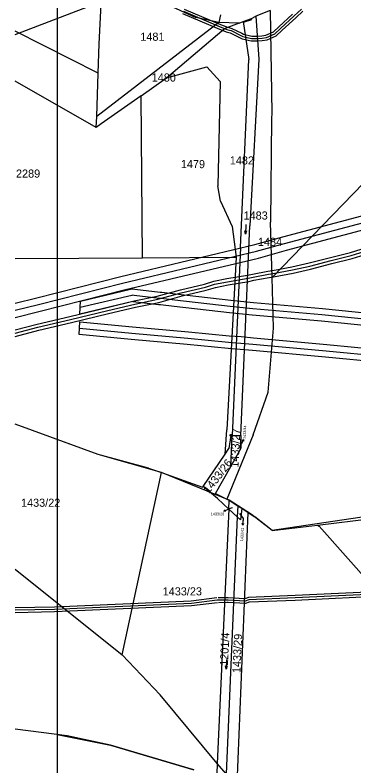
# Model space of a CAD drawing. Extents: x -510185 to -506993, y -1126306 to -1123642.
# Drawn here: x -510185 to -509972.3, y -1125827.4 to -1125355.5 of the extents above; entities that cross this region are included whole.
import ezdxf

# ---------------------------------------------------------------- set-up
doc = ezdxf.new("R2010")
doc.units = 0
for name, color, linetype in [('Net4gas', 7, 'Continuous'), ('parcelni hranice', 7, 'Continuous'), ('telefonica', 7, 'Continuous'), ('u_dalnice', 7, 'Continuous'), ('u_kabely', 7, 'Continuous'), ('u_net4gas', 7, 'Continuous'), ('u_plyn ochranné pásmo', 7, 'Continuous'), ('u_plyn VTL', 7, 'Continuous'), ('u_sitel_self_net4', 7, 'Continuous'), ('u_Telefonica', 7, 'Continuous'), ('x_formát_rám', 7, 'Continuous'), ('ČEPS', 7, 'Continuous'), ('ˇ2', 7, 'Continuous'), ('ˇ3', 7, 'Continuous'), ('ˇ4', 7, 'Continuous'), ('ˇ7', 7, 'Continuous'), ('ˇ8', 7, 'Continuous')]:
    doc.layers.add(name, color=color, linetype=linetype)

msp = doc.modelspace()

# ---------------------------------------------------------------- linework, layer by layer
at = {"layer": 'Net4gas'}
for points in [[(-510185.05, -1125536.53), (-510171.45, -1125533.15), (-510118.64, -1125519.73), (-510034.51, -1125499.78), (-510017.05, -1125494.96), (-509964.2, -1125480.91), (-509918.3, -1125468.33), (-509886.05, -1125459.17), (-509862.65, -1125451.75), (-509848.66, -1125447.37)], [(-510185.05, -1125545.5), (-510169.33, -1125541.59), (-510116.57, -1125528.18), (-510032.35, -1125508.21), (-510014.78, -1125503.35), (-509961.93, -1125489.31), (-509915.96, -1125476.71), (-509883.55, -1125467.5), (-509860.03, -1125460.04), (-509848.72, -1125456.5), (-509843.6, -1125454.45), (-509839.38, -1125452.47), (-509835.66, -1125450.19)]]:
    msp.add_lwpolyline(points, dxfattribs=at)
at = {"layer": 'parcelni hranice'}
for p, q in [((-510132.16, -1125373.62), (-510129.92, -1125327.14)), ((-510096.36, -1125345.63), (-510071.49, -1125357.11)), ((-510025, -1125352.59), (-510033.87, -1125356.33)), ((-510025, -1125352.59), (-510023.92, -1125417.04)), ((-510057.09, -1125360.29), (-510071.49, -1125357.11)), ((-510056.1, -1125355.49), (-510057.09, -1125360.29)), ((-510041.95, -1125359.51), (-510036.6, -1125357.7)), ((-510036.6, -1125357.7), (-510033.87, -1125356.33)), ((-510033.87, -1125356.33), (-510032.03, -1125383.35)), ((-510057.09, -1125360.29), (-510133.77, -1125419.38)), ((-510044.29, -1125360.72), (-510057.09, -1125360.29)), ((-510044.29, -1125360.72), (-510053.82, -1125364.11)), ((-510044.29, -1125360.72), (-510041.95, -1125359.51)), ((-510041.95, -1125359.51), (-510038.29, -1125383.47)), ((-510132.81, -1125392.03), (-510185.05, -1125365.7)), ((-510090, -1125395), (-510053.82, -1125364.11)), ((-510132.81, -1125392.03), (-510132.16, -1125373.62)), ((-510043.54, -1125501.56), (-510038.29, -1125383.47)), ((-510032.03, -1125383.35), (-510037.65, -1125487.99)), ((-510133.77, -1125419.38), (-510132.81, -1125392.03)), ((-510090, -1125395), (-510064.59, -1125388.14)), ((-510064.59, -1125388.14), (-510056.37, -1125397.34)), ((-510105.97, -1125406.29), (-510090, -1125395)), ((-510134.23, -1125426.27), (-510185.05, -1125397.03)), ((-510056.37, -1125397.34), (-510057.72, -1125462.78)), ((-510105.97, -1125406.29), (-510130.91, -1125423.92)), ((-510105.03, -1125508.07), (-510105.97, -1125406.29)), ((-510134.23, -1125426.27), (-510133.77, -1125419.38)), ((-510023.92, -1125417.04), (-510024.09, -1125420.78)), ((-510130.91, -1125423.92), (-510134.23, -1125426.27)), ((-510024.09, -1125420.78), (-510024.78, -1125485.7)), ((-510056.06, -1125472.49), (-510057.72, -1125462.78)), ((-510023.75, -1125520.46), (-509966.3, -1125461.11)), ((-510056.06, -1125472.49), (-510048.68, -1125488.4)), ((-510023.75, -1125520.46), (-510024.78, -1125485.7)), ((-510048.68, -1125488.4), (-510046.34, -1125507.71)), ((-510043.38, -1125619.76), (-510037.65, -1125487.99)), ((-510043.54, -1125501.56), (-510048.8, -1125619.64)), ((-510185.05, -1125508.57), (-510105.03, -1125508.07)), ((-510105.03, -1125508.07), (-510046.34, -1125507.71)), ((-510046.34, -1125507.71), (-510052.18, -1125616.15)), ((-510022.8, -1125552.26), (-510023.75, -1125520.46)), ((-510026.11, -1125592.58), (-510022.8, -1125552.26)), ((-510035.59, -1125619.37), (-510026.11, -1125592.58)), ((-510132.83, -1125631.61), (-510185.05, -1125612.65)), ((-510053.19, -1125631.35), (-510052.18, -1125616.15)), ((-510035.59, -1125619.37), (-510052.16, -1125659.63)), ((-510049.55, -1125619.62), (-510050.81, -1125627.83)), ((-510049.68, -1125639.15), (-510048.8, -1125619.64)), ((-510049.55, -1125619.62), (-510048.8, -1125619.64)), ((-510048.8, -1125619.64), (-510043.38, -1125619.76)), ((-510043.38, -1125619.76), (-510043.77, -1125628.66)), ((-510043.38, -1125619.76), (-510043.03, -1125619.77)), ((-510043.03, -1125627.35), (-510043.03, -1125619.77)), ((-510053.19, -1125631.35), (-510050.81, -1125627.83)), ((-510043.77, -1125628.66), (-510043.03, -1125627.35)), ((-510101.36, -1125640.14), (-510132.83, -1125631.61)), ((-510066.96, -1125651.71), (-510053.19, -1125631.35)), ((-510049.68, -1125639.15), (-510043.77, -1125628.66)), ((-510101.36, -1125640.14), (-510093.14, -1125643.06)), ((-510059.22, -1125656.07), (-510049.68, -1125639.15)), ((-510117.75, -1125757.56), (-510093.14, -1125643.06)), ((-510093.14, -1125643.06), (-510067.31, -1125652.23)), ((-510067.31, -1125652.23), (-510066.96, -1125651.71)), ((-510058.07, -1125659.4), (-510066.96, -1125651.71)), ((-510059.22, -1125656.07), (-510052.16, -1125659.63)), ((-510050.89, -1125665.93), (-510058.07, -1125659.4)), ((-510052.16, -1125659.63), (-510050.64, -1125660.39)), ((-510050.89, -1125665.93), (-510050.64, -1125660.39)), ((-510050.64, -1125660.39), (-510045.3, -1125663.84)), ((-510045.3, -1125663.84), (-510045.6, -1125670.75)), ((-510045.3, -1125663.84), (-510042.8, -1125665.45)), ((-510042.8, -1125665.45), (-510043.45, -1125672.71)), ((-510042.8, -1125665.45), (-510038.8, -1125668.01)), ((-510050.89, -1125665.93), (-510058.1, -1125825.76)), ((-510045.6, -1125670.75), (-510050.89, -1125665.93)), ((-510045.7, -1125840.66), (-510038.8, -1125668.01)), ((-510038.8, -1125668.01), (-510034.55, -1125670.75)), ((-510045.6, -1125670.75), (-510052.62, -1125832.34)), ((-510043.45, -1125672.71), (-510045.6, -1125670.75)), ((-510023.73, -1125679.44), (-510034.55, -1125670.75)), ((-509995.13, -1125675.96), (-509950.93, -1125670.58)), ((-510023.73, -1125679.44), (-509995.13, -1125675.96)), ((-509995.13, -1125675.96), (-509994.25, -1125676.78)), ((-509994.25, -1125676.78), (-509931.26, -1125747.67)), ((-510185.05, -1125703.64), (-510117.75, -1125757.56)), ((-510093.92, -1125782.72), (-510117.75, -1125757.56)), ((-510058.1, -1125825.76), (-510093.92, -1125782.72)), ((-510185.02, -1125804.26), (-510185.05, -1125804.26)), ((-510152.27, -1125808.45), (-510185.02, -1125804.26)), ((-510125.17, -1125814.3), (-510152.27, -1125808.45)), ((-510072.92, -1125829.82), (-510125.17, -1125814.3)), ((-510058.1, -1125825.76), (-510058.76, -1125840.4)), ((-510052.62, -1125832.34), (-510058.1, -1125825.76))]:
    msp.add_line(p, q, dxfattribs=at)
at = {"layer": 'telefonica'}
for points in [[(-510079.95, -1125354.56), (-510058.26, -1125363.77), (-510052.63, -1125365.99), (-510050.96, -1125366.46), (-510050.01, -1125366.72), (-510044.11, -1125369.69), (-510042.61, -1125370.44), (-510036.77, -1125371.74), (-510032.86, -1125371.75), (-510029.9, -1125371.48), (-510026.9, -1125371.21), (-510021.07, -1125368.54), (-510017.4, -1125365.12), (-510008.89, -1125357.2), (-510004.36, -1125353.02)], [(-510078.83, -1125351.78), (-510057.12, -1125360.99), (-510051.67, -1125363.15), (-510050.16, -1125363.56), (-510048.93, -1125363.9), (-510042.76, -1125367.01), (-510041.59, -1125367.6), (-510036.43, -1125368.74), (-510033, -1125368.75), (-510030.18, -1125368.5), (-510027.68, -1125368.27), (-510022.77, -1125366.02), (-510019.44, -1125362.92), (-510010.93, -1125355)], [(-509950.22, -1125717.48), (-510009.33, -1125720.31), (-510038.57, -1125721.51), (-510040.86, -1125722.29), (-510051.26, -1125721.67), (-510052.1, -1125721.71), (-510057.48, -1125721.75)], [(-510058.34, -1125721.79), (-510074.52, -1125723.71), (-510117.42, -1125725.72), (-510160.36, -1125727.52), (-510185.05, -1125728.05)], [(-509950.08, -1125720.48), (-510009.2, -1125723.31), (-510038.01, -1125724.49), (-510040.45, -1125725.32), (-510051.28, -1125724.68), (-510052.03, -1125724.71), (-510057.46, -1125724.75)], [(-510057.99, -1125724.77), (-510074.28, -1125726.7), (-510117.29, -1125728.71), (-510160.27, -1125730.52), (-510185.05, -1125731.05)]]:
    msp.add_lwpolyline(points, dxfattribs=at)
at = {"layer": 'u_dalnice'}
msp.add_lwpolyline([(-509237.51, -1125457.2), (-509274.25, -1125471.43), (-509314.64, -1125490.19), (-509337.52, -1125503.75), (-509419.1, -1125540.14), (-509491.5, -1125569.97), (-509564.07, -1125593.54), (-509583.54, -1125598.65), (-509619.19, -1125610.65), (-509686.76, -1125629.97), (-509845.55, -1125665.85), (-509878.2, -1125657.82), (-510023.73, -1125679.44), (-510036.67, -1125669.38), (-510050.64, -1125660.39), (-510093.14, -1125643.06), (-510132.83, -1125631.61), (-510158.52, -1125622.28), (-510158.52, -1125807.65), (-510125.17, -1125814.3), (-510072.92, -1125829.82)], dxfattribs=at)
at = {"layer": 'u_kabely'}
for points in [[(-510185.05, -1125553.4), (-510171.14, -1125549.71), (-510150.63, -1125544.87), (-510127.22, -1125539.2), (-510110.21, -1125535.2), (-510095.82, -1125532.21), (-510081.26, -1125528.18), (-510066.1, -1125524.62), (-510060.33, -1125522.77), (-510052.05, -1125521.17), (-510039.1, -1125518.99), (-510036.06, -1125518.29), (-510026.33, -1125516.41), (-510023.46, -1125515.99), (-510011.4, -1125513.73), (-510000.55, -1125511.28), (-509987.12, -1125507.77), (-509974.54, -1125504.72), (-509961.03, -1125500.52)], [(-510185.05, -1125557.54), (-510170.16, -1125553.59), (-510149.71, -1125548.77), (-510126.3, -1125543.1), (-510109.35, -1125539.1), (-510094.88, -1125536.09), (-510080.26, -1125532.06), (-510065.04, -1125528.48), (-510059.33, -1125526.65), (-510051.33, -1125525.11), (-510038.32, -1125522.91), (-510035.24, -1125522.21), (-510025.65, -1125520.35), (-510022.8, -1125519.93), (-510010.6, -1125517.65), (-509999.61, -1125515.16), (-509986.14, -1125511.65), (-509973.48, -1125508.58), (-509959.85, -1125504.34)]]:
    msp.add_lwpolyline(points, dxfattribs=at)
at = {"layer": 'u_net4gas'}
msp.add_lwpolyline([(-510185.05, -1125541.01), (-510170.39, -1125537.37), (-510117.6, -1125523.96), (-510033.43, -1125503.99), (-510015.92, -1125499.15), (-509963.07, -1125485.11), (-509917.13, -1125472.52), (-509884.8, -1125463.34), (-509861.34, -1125455.9), (-509850.18, -1125452.4), (-509845.33, -1125450.46), (-509841.45, -1125448.64), (-509837.93, -1125446.48)], dxfattribs=at)
at = {"layer": 'u_plyn ochranné pásmo'}
for points in [[(-509953.91, -1125551.85), (-509992.81, -1125547.93), (-510036.13, -1125544.04), (-510050.56, -1125542.69), (-510085.23, -1125538.68), (-510093.8, -1125537.71), (-510094.92, -1125537.58), (-510110.85, -1125535.64), (-510111.11, -1125535.61), (-510111.15, -1125535.61), (-510144.29, -1125543.54), (-510143.95, -1125535.23), (-510112.51, -1125527.71), (-510111.03, -1125527.55), (-510109.87, -1125527.7), (-510094, -1125529.64), (-510092.92, -1125529.76), (-510084.31, -1125530.74), (-510049.72, -1125534.73), (-510035.39, -1125536.08), (-509992.05, -1125539.97), (-509953.11, -1125543.89)], [(-509955.3, -1125573.76), (-509990.18, -1125570.56), (-510036.12, -1125566.28), (-510043.73, -1125565.58), (-510051.39, -1125564.96), (-510076.95, -1125562.64), (-510112.08, -1125559.45), (-510144.81, -1125556.35), (-510144.48, -1125548.34), (-510111.34, -1125551.49), (-510076.23, -1125554.68), (-510050.71, -1125556.99), (-510043.03, -1125557.61), (-510035.38, -1125558.32), (-509989.44, -1125562.6), (-509954.56, -1125565.8)]]:
    msp.add_lwpolyline(points, dxfattribs=at)
at = {"layer": 'u_plyn VTL'}
for points in [[(-510111.07, -1125531.58), (-510111.83, -1125531.66), (-510144.12, -1125539.38)], [(-509698.12, -1125574.63), (-509699.29, -1125574.12), (-509751.89, -1125568.73), (-509804.32, -1125563.27), (-509856.68, -1125557.63), (-509905.92, -1125552.72), (-509953.51, -1125547.87), (-509992.43, -1125543.95), (-510035.76, -1125540.06), (-510050.14, -1125538.71), (-510084.77, -1125534.71), (-510093.36, -1125533.73), (-510094.46, -1125533.61), (-510110.36, -1125531.67), (-510111.07, -1125531.58)], [(-510144.65, -1125552.35), (-510111.71, -1125555.47), (-510076.59, -1125558.66), (-510051.05, -1125560.97), (-510043.38, -1125561.6), (-510035.75, -1125562.3), (-509989.81, -1125566.58), (-509954.93, -1125569.78), (-509902.55, -1125574.61), (-509850.15, -1125579.63), (-509797.56, -1125584.44), (-509754.73, -1125588.32), (-509715.49, -1125591.59), (-509713.82, -1125591.79), (-509712.82, -1125592.34)]]:
    msp.add_lwpolyline(points, dxfattribs=at)
at = {"layer": 'u_sitel_self_net4'}
msp.add_lwpolyline([(-510185.05, -1125555.47), (-510170.65, -1125551.65), (-510150.17, -1125546.82), (-510126.76, -1125541.15), (-510109.78, -1125537.15), (-510095.35, -1125534.15), (-510080.76, -1125530.12), (-510065.57, -1125526.55), (-510059.83, -1125524.71), (-510051.69, -1125523.14), (-510038.71, -1125520.95), (-510035.65, -1125520.25), (-510025.99, -1125518.38), (-510023.13, -1125517.96), (-510011, -1125515.69), (-510000.08, -1125513.22), (-509986.63, -1125509.71), (-509974.01, -1125506.65), (-509960.44, -1125502.43)], dxfattribs=at)
msp.add_lwpolyline([(-510185.05, -1125555.47), (-510170.65, -1125551.65), (-510150.17, -1125546.82), (-510126.76, -1125541.15), (-510109.78, -1125537.15), (-510095.35, -1125534.15), (-510080.76, -1125530.12), (-510065.57, -1125526.55), (-510059.83, -1125524.71), (-510051.69, -1125523.14), (-510038.71, -1125520.95), (-510035.65, -1125520.25), (-510025.99, -1125518.38), (-510023.13, -1125517.96), (-510011, -1125515.69), (-510000.08, -1125513.22), (-509986.63, -1125509.71), (-509974.01, -1125506.65), (-509960.44, -1125502.43)], dxfattribs=at)
msp.add_lwpolyline([(-510185.05, -1125555.47), (-510170.65, -1125551.65), (-510150.17, -1125546.82), (-510126.76, -1125541.15), (-510109.78, -1125537.15), (-510095.35, -1125534.15), (-510080.76, -1125530.12), (-510065.57, -1125526.55), (-510059.83, -1125524.71), (-510051.69, -1125523.14), (-510038.71, -1125520.95), (-510035.65, -1125520.25), (-510025.99, -1125518.38), (-510023.13, -1125517.96), (-510011, -1125515.69), (-510000.08, -1125513.22), (-509986.63, -1125509.71), (-509974.01, -1125506.65), (-509960.44, -1125502.43)], dxfattribs=at)
at = {"layer": 'u_Telefonica'}
for p, q in [((-510057.69, -1125362.38), (-510052.15, -1125364.57)), ((-510057.69, -1125362.38), (-510052.15, -1125364.57)), ((-510057.47, -1125723.25), (-510058.17, -1125723.28)), ((-510057.47, -1125723.25), (-510058.17, -1125723.28))]:
    msp.add_line(p, q, dxfattribs=at)
for points in [[(-510079.39, -1125353.17), (-510057.69, -1125362.38), (-510052.15, -1125364.57), (-510050.56, -1125365.01), (-510049.47, -1125365.31), (-510043.43, -1125368.35), (-510042.1, -1125369.02), (-510036.6, -1125370.24), (-510032.93, -1125370.25), (-510030.04, -1125369.99), (-510027.29, -1125369.74), (-510021.92, -1125367.28), (-510018.42, -1125364.02), (-510009.91, -1125356.1), (-510005.29, -1125351.84)], [(-510079.39, -1125353.17), (-510057.69, -1125362.38), (-510052.15, -1125364.57), (-510050.56, -1125365.01), (-510049.47, -1125365.31), (-510043.43, -1125368.35), (-510042.1, -1125369.02), (-510036.6, -1125370.24), (-510032.93, -1125370.25), (-510030.04, -1125369.99), (-510027.29, -1125369.74), (-510021.92, -1125367.28), (-510018.42, -1125364.02), (-510009.91, -1125356.1), (-510005.29, -1125351.84)], [(-510079.39, -1125353.17), (-510057.69, -1125362.38), (-510052.15, -1125364.57), (-510050.56, -1125365.01), (-510049.47, -1125365.31), (-510043.43, -1125368.35), (-510042.1, -1125369.02), (-510036.6, -1125370.24), (-510032.93, -1125370.25), (-510030.04, -1125369.99), (-510027.29, -1125369.74), (-510021.92, -1125367.28), (-510018.42, -1125364.02), (-510009.91, -1125356.1), (-510005.29, -1125351.84)], [(-510079.39, -1125353.17), (-510057.69, -1125362.38), (-510052.15, -1125364.57), (-510050.56, -1125365.01), (-510049.47, -1125365.31), (-510043.43, -1125368.35), (-510042.1, -1125369.02), (-510036.6, -1125370.24), (-510032.93, -1125370.25), (-510030.04, -1125369.99), (-510027.29, -1125369.74), (-510021.92, -1125367.28), (-510018.42, -1125364.02), (-510009.91, -1125356.1), (-510005.29, -1125351.84)], [(-510042.1, -1125369.02), (-510036.6, -1125370.24), (-510032.93, -1125370.25)], [(-510042.1, -1125369.02), (-510036.6, -1125370.24), (-510032.93, -1125370.25)], [(-509950.15, -1125718.98), (-510009.26, -1125721.81), (-510038.29, -1125723), (-510040.66, -1125723.8), (-510051.27, -1125723.18), (-510052.07, -1125723.21), (-510057.47, -1125723.25)], [(-509950.15, -1125718.98), (-510009.26, -1125721.81), (-510038.29, -1125723), (-510040.66, -1125723.8), (-510051.27, -1125723.18), (-510052.07, -1125723.21), (-510057.47, -1125723.25)], [(-510058.17, -1125723.28), (-510074.4, -1125725.21), (-510117.35, -1125727.22), (-510160.31, -1125729.02), (-510185.05, -1125729.55)], [(-510058.17, -1125723.28), (-510074.4, -1125725.21), (-510117.35, -1125727.22), (-510160.31, -1125729.02), (-510185.05, -1125729.55)]]:
    msp.add_lwpolyline(points, dxfattribs=at)
at = {"layer": 'x_formát_rám'}
msp.add_lwpolyline([(-510158.52, -1126278.21), (-507008.52, -1126278.21), (-507008.52, -1123673.61), (-510158.52, -1123673.61)], close=True, dxfattribs=at)
at = {"layer": 'ČEPS'}
msp.add_lwpolyline([(-510185.05, -1125367.76), (-510002.86, -1125297.71), (-509683.9, -1125222.3), (-509360.43, -1125146.6), (-509044.57, -1125071.75), (-508717.34, -1124994.86), (-508389.12, -1124921.16), (-508070.72, -1124848.1), (-507890, -1124804.52)], dxfattribs=at)
at = {"layer": 'ˇ3'}
for points in [[(-510040.18, -1125487.19), (-510040.46, -1125493.19)], [(-510039.87, -1125491.21), (-510040.46, -1125493.19), (-510040.86, -1125491.17)], [(-510051.92, -1125764.48), (-510052.5, -1125766.46), (-510052.91, -1125764.44)], [(-510052.24, -1125760.46), (-510052.5, -1125766.46)]]:
    msp.add_lwpolyline(points, dxfattribs=at)
at = {"layer": 'ˇ4'}
for p, q in [((-510041.73, -1125360.07), (-510036.47, -1125358.32)), ((-510036.47, -1125358.32), (-510036.6, -1125357.7)), ((-510041.95, -1125359.51), (-510041.73, -1125360.07))]:
    msp.add_line(p, q, dxfattribs=at)
at = {"layer": 'ˇ7'}
for p, q in [((-510043.47, -1125626), (-510042.92, -1125624.87)), ((-510048.85, -1125665.13), (-510051.19, -1125666.09)), ((-510044.27, -1125668.65), (-510041.81, -1125671.82)), ((-510041.81, -1125671.82), (-510041.91, -1125673.06))]:
    msp.add_line(p, q, dxfattribs=at)
for points in [[(-510041.61, -1125622.17), (-510042.92, -1125624.87)], [(-510042.5, -1125622.85), (-510041.61, -1125622.17), (-510041.6, -1125623.29)], [(-510053.96, -1125667.24), (-510051.19, -1125666.09)], [(-510052.85, -1125667.32), (-510053.96, -1125667.24), (-510053.23, -1125666.39)], [(-510041.58, -1125675.09), (-510042.16, -1125676.05), (-510042.58, -1125675.01)], [(-510042.16, -1125676.05), (-510041.91, -1125673.06)]]:
    msp.add_lwpolyline(points, dxfattribs=at)
at = {"layer": 'ˇ8'}
msp.add_lwpolyline([(-510049.4, -1125619.14), (-510049.15, -1125619.33), (-510049.05, -1125619.62), (-510049.15, -1125619.91), (-510049.4, -1125620.1), (-510049.7, -1125620.1), (-510049.95, -1125619.91), (-510050.05, -1125619.62), (-510049.95, -1125619.33), (-510049.7, -1125619.14)], close=True, dxfattribs=at)
msp.add_lwpolyline([(-510049.67, -1125619.62), (-510049.43, -1125619.62)], dxfattribs=at)

# ---------------------------------------------------------------- texts
at = {"layer": 'ˇ2'}
for s, height, p in [('1481', 5.1, (-510106.42, -1125371.7)), ('1480', 5.1, (-510099.29, -1125397.33)), ('1479', 5.1, (-510080.98, -1125451.73)), ('1482', 5.1, (-510050.27, -1125449.43)), ('2289', 5.1, (-510184.45, -1125457.69)), ('1483', 5.1, (-510041.63, -1125484.06)), ('1484', 5.1, (-510032.6, -1125500.6)), ('1433/44', 0.3, (-510044.29, -1125626)), ('1433/22', 5.1, (-510181.29, -1125664.5)), ('1433/28', 0.3, (-510049.68, -1125665.13)), ('1433/43', 0.3, (-510045.1, -1125668.65)), ('1433/23', 5.1, (-510092.39, -1125720.19))]:
    msp.add_text(s, height=height, dxfattribs=at).set_placement(p)
for s, rotation, p in [('1433/27', 86.8031, (-510044.9, -1125640.03)), ('1433/26', 52.1965, (-510063.43, -1125656.53)), ('1201/4', 87.3188, (-510051.45, -1125764.51)), ('1433/29', 87.3761, (-510043.6, -1125769.07))]:
    msp.add_text(s, height=5.1, rotation=rotation, dxfattribs=at).set_placement(p)
at = {"layer": 'ˇ7'}
for s, rotation, p in [('1433/44', 87.949, (-510040.25, -1125621.89)), ('1433/43', 86.2874, (-510041.94, -1125686.24))]:
    msp.add_text(s, height=1.7, rotation=rotation, dxfattribs=at).set_placement(p)
msp.add_text('1433/28', height=1.7, dxfattribs=at).set_placement((-510062.21, -1125669.89))

doc.saveas('drawing.dxf')
